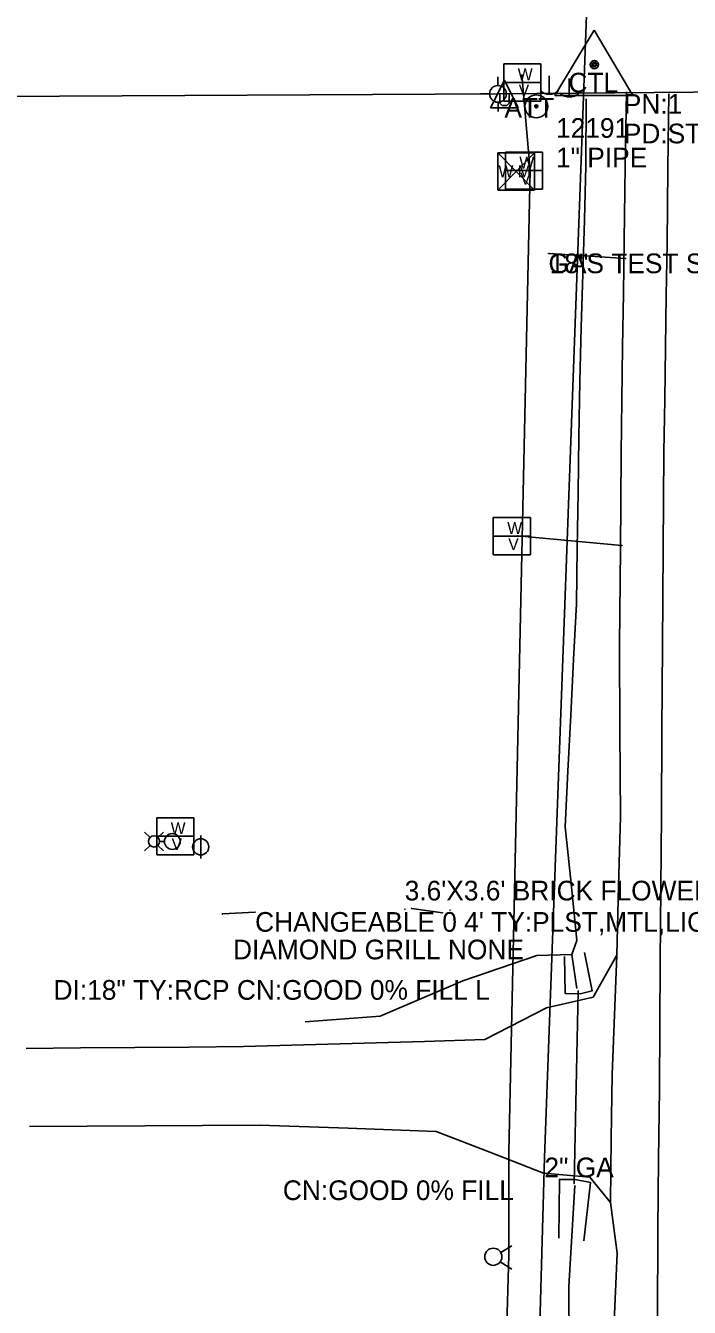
# Model space of a CAD drawing. Extents: x 1707085 to 1720058, y 548761 to 560063.
# Drawn here: x 1712324.4 to 1712493.1, y 550824.4 to 551149.9 of the extents above; entities that cross this region are included whole.
import ezdxf

# ---------------------------------------------------------------- set-up
doc = ezdxf.new("R2010")
doc.units = 0
for name, color, linetype in [('3', 7, 'Continuous'), ('R_Contour Annot', 7, 'Continuous'), ('R_Horz Alg Annot', 7, 'Continuous'), ('R_Water Annot', 7, 'Continuous'), ('S_DRG_PT_SYM', 7, 'Continuous'), ('S_DRIVEWAY', 7, 'Continuous'), ('S_EDGE_CONCRETE', 7, 'Continuous'), ('S_EDGE_PAVEMENT', 7, 'Continuous'), ('S_GAS_UTILITIES', 7, 'Continuous'), ('S_GAS_UTILITIES_ANNOT', 7, 'Continuous'), ('S_IRON_PIN', 7, 'Continuous'), ('S_IRON_PIN_ANNOT', 7, 'Continuous'), ('S_MISC_STRUCTURES_ANNOT', 7, 'Continuous'), ('S_MSC_PT_SYM', 7, 'Continuous'), ('S_PAVEMENT_CROWN', 7, 'Continuous'), ('S_PRIMARY_CTL_ANNOT', 7, 'Continuous'), ('S_SIDE_DRAIN_ANNOT', 7, 'Continuous'), ('S_SIGN_ANNOT', 7, 'Continuous'), ('S_UNDERGROUND_CABLE', 7, 'Continuous'), ('S_UTILITY_POLE', 7, 'Continuous'), ('S_UTILITY_POLE_ANNOT', 7, 'Continuous'), ('S_UTL_PT_SYM', 7, 'Continuous')]:
    doc.layers.add(name, color=color, linetype=linetype)

msp = doc.modelspace()

# ---------------------------------------------------------------- linework, layer by layer
for points in [[(1712464.5, 550905.39), (1712463.25, 550914.02), (1712464.48, 550917.63), (1712463.01, 550932.04), (1712461.53, 550946.44), (1712462.24, 550960.61), (1712462.94, 550974.77), (1712463.65, 550988.93), (1712464.36, 551003.09), (1712464.57, 551017.21), (1712464.79, 551031.33), (1712465.01, 551045.44), (1712465.23, 551059.56), (1712465.62, 551073.23), (1712466.02, 551086.9), (1712466.41, 551100.57), (1712466.81, 551114.24), (1712466.83, 551131.33)], [(1712463.25, 550914.02), (1712454.36, 550913.82), (1712435.52, 550907.35), (1712414.54, 550898.36), (1712395.46, 550896.92)], [(1712463.94, 550855.4), (1712463.2, 550842.56), (1712462.46, 550829.72), (1712462.55, 550815.13), (1712462.64, 550800.54), (1712462.46, 550798.31), (1712462.44, 550791.97), (1712462.37, 550776.28), (1712462.3, 550760.58), (1712462.68, 550740.27), (1712463.06, 550719.96), (1712463.44, 550699.64), (1712463.81, 550679.33), (1712464.04, 550656.46), (1712464.27, 550633.6), (1712455.29, 550618.31)]]:
    msp.add_lwpolyline(points)
at = {"layer": '3'}
msp.add_line((1712464.83, 550904.77), (1712463.8, 550855.94), dxfattribs=at)
at = {"layer": 'R_Contour Annot'}
for p, q in [((1712468.92, 551148.69), (1712458.89, 551132.17)), ((1712468.92, 551148.69), (1712478.75, 551132.17)), ((1712458.89, 551132.17), (1712478.75, 551132.17))]:
    msp.add_line(p, q, dxfattribs=at)
for radius in [1.04, 0.609, 0.344]:
    msp.add_circle((1712468.92, 551139.99), radius, dxfattribs=at)
at = {"layer": 'R_Horz Alg Annot'}
for p, q in [((1712430.31, 550924.65), (1712422.52, 550925.73)), ((1712382.73, 550924.81), (1712374.42, 550924.33))]:
    msp.add_line(p, q, dxfattribs=at)
at = {"layer": 'R_Water Annot'}
for p, q in [((1712445.92, 551140.15), (1712455.34, 551140.15)), ((1712445.92, 551130.74), (1712445.92, 551140.15)), ((1712455.34, 551140.15), (1712455.34, 551130.74)), ((1712452.6, 551113.03), (1712450.52, 551137.37)), ((1712445.92, 551135.47), (1712455.34, 551135.47)), ((1712455.34, 551130.74), (1712445.92, 551130.74)), ((1712444.37, 551117.62), (1712453.71, 551117.62)), ((1712444.37, 551117.62), (1712444.37, 551108.13)), ((1712444.37, 551117.62), (1712453.71, 551108.13)), ((1712453.71, 551117.62), (1712444.37, 551108.13)), ((1712446.32, 551117.74), (1712455.74, 551117.74)), ((1712446.32, 551108.33), (1712446.32, 551117.74)), ((1712453.71, 551117.62), (1712453.71, 551108.13)), ((1712455.74, 551117.74), (1712455.74, 551108.33)), ((1712446.32, 551113.06), (1712455.74, 551113.06)), ((1712447.18, 550863.91), (1712452.6, 551113.03)), ((1712444.37, 551108.13), (1712453.71, 551108.13)), ((1712455.74, 551108.33), (1712446.32, 551108.33)), ((1712443.26, 551024.96), (1712452.68, 551024.96)), ((1712443.26, 551015.55), (1712443.26, 551024.96)), ((1712452.68, 551024.96), (1712452.68, 551015.55)), ((1712443.26, 551020.28), (1712452.68, 551020.28)), ((1712449.37, 551020.3), (1712475.96, 551017.85)), ((1712452.68, 551015.55), (1712443.26, 551015.55)), ((1712357.72, 550948.78), (1712367.13, 550948.78)), ((1712357.72, 550939.37), (1712357.72, 550948.78)), ((1712367.13, 550948.78), (1712367.13, 550939.37)), ((1712357.72, 550944.09), (1712367.13, 550944.09)), ((1712367.13, 550939.37), (1712357.72, 550939.37)), ((1712447.19, 550837.71), (1712447.18, 550863.91)), ((1712445.16, 550838.36), (1712447.98, 550840.09)), ((1712446.27, 550804), (1712447.19, 550837.71)), ((1712445.03, 550836.05), (1712447.94, 550834.12))]:
    msp.add_line(p, q, dxfattribs=at)
msp.add_circle((1712443.25, 550837.3), 2.18, dxfattribs=at)
at = {"layer": 'S_DRG_PT_SYM'}
for points in [[(1712464.83, 550904.77), (1712464.83, 550904.82), (1712464.83, 550904.77), (1712464.78, 550904.77), (1712464.83, 550904.77), (1712464.83, 550904.72), (1712464.83, 550904.77), (1712464.88, 550904.77)], [(1712463.8, 550855.94), (1712463.8, 550855.99), (1712463.8, 550855.94), (1712463.75, 550855.94), (1712463.8, 550855.94), (1712463.8, 550855.89), (1712463.8, 550855.94), (1712463.85, 550855.94)]]:
    msp.add_lwpolyline(points, dxfattribs=at)
at = {"layer": 'S_DRIVEWAY'}
for points in [[(1712324.57, 550890.19), (1712338.36, 550890.31), (1712352.16, 550890.43), (1712365.95, 550890.55), (1712379.74, 550890.67), (1712395.09, 550891.11), (1712410.44, 550891.55), (1712425.79, 550891.99), (1712441.14, 550892.43), (1712456.77, 550900.53), (1712468.64, 550903.23), (1712474.64, 550913.89)], [(1712473.03, 550851.08), (1712467.79, 550857.49), (1712455.99, 550858.53), (1712442.36, 550863.82), (1712428.73, 550869.12), (1712406.35, 550869.92), (1712383.97, 550870.71), (1712369.34, 550870.62), (1712354.71, 550870.53), (1712340.08, 550870.44), (1712325.44, 550870.35)]]:
    msp.add_lwpolyline(points, dxfattribs=at)
at = {"layer": 'S_EDGE_CONCRETE'}
for points in [[(1712461.36, 550913.56), (1712461.5, 550904.18), (1712465.31, 550904.06), (1712468.42, 550904.84), (1712466.46, 550914.55)], [(1712459.94, 550842.02), (1712460.08, 550856.92), (1712464.09, 550856.95), (1712467.97, 550856.15), (1712466.25, 550841.33)]]:
    msp.add_lwpolyline(points, dxfattribs=at)
at = {"layer": 'S_EDGE_PAVEMENT'}
msp.add_lwpolyline([(1712477.08, 551133.03), (1712476.81, 551114.23), (1712476.55, 551095.42), (1712476.34, 551081.87), (1712476.13, 551068.31), (1712475.92, 551054.75), (1712475.71, 551041.2), (1712475.54, 551016.98), (1712475.36, 550992.76), (1712475.45, 550970.88), (1712475.54, 550949), (1712475.09, 550931.44), (1712474.64, 550913.89), (1712474.06, 550898.74), (1712473.47, 550883.58), (1712473.25, 550867.33), (1712473.03, 550851.08), (1712474.71, 550838.17), (1712473.92, 550818.83)], dxfattribs=at)
at = {"layer": 'S_GAS_UTILITIES'}
for p, q in [((1712471.24, 551268.07), (1712456.25, 550862.48)), ((1712457.58, 551092.02), (1712476.87, 551090.75)), ((1712456.25, 550862.48), (1712454.33, 550794.95))]:
    msp.add_line(p, q, dxfattribs=at)
at = {"layer": 'S_IRON_PIN'}
for radius in [2.91, 0.411, 0.262, 0.212, 0.145, 0.0822, 0.0581]:
    msp.add_circle((1712454.19, 551129.39), radius, dxfattribs=at)
at = {"layer": 'S_MSC_PT_SYM'}
for points in [[(1712457.27, 551092.02), (1712457.27, 551092.07), (1712457.27, 551092.02), (1712457.22, 551092.02), (1712457.27, 551092.02), (1712457.27, 551091.97), (1712457.27, 551092.02), (1712457.32, 551092.02)], [(1712420.81, 550925.53), (1712420.81, 550925.58), (1712420.81, 550925.53), (1712420.76, 550925.53), (1712420.81, 550925.53), (1712420.81, 550925.48), (1712420.81, 550925.53), (1712420.86, 550925.53)], [(1712422.52, 550925.73), (1712422.52, 550925.78), (1712422.52, 550925.73), (1712422.47, 550925.73), (1712422.52, 550925.73), (1712422.52, 550925.68), (1712422.52, 550925.73), (1712422.57, 550925.73)], [(1712432.28, 550925.33), (1712432.28, 550925.38), (1712432.28, 550925.33), (1712432.23, 550925.33), (1712432.28, 550925.33), (1712432.28, 550925.28), (1712432.28, 550925.33), (1712432.33, 550925.33)], [(1712374.42, 550924.33), (1712374.42, 550924.38), (1712374.42, 550924.33), (1712374.37, 550924.33), (1712374.42, 550924.33), (1712374.42, 550924.28), (1712374.42, 550924.33), (1712374.47, 550924.33)], [(1712382.73, 550924.81), (1712382.73, 550924.86), (1712382.73, 550924.81), (1712382.68, 550924.81), (1712382.73, 550924.81), (1712382.73, 550924.76), (1712382.73, 550924.81), (1712382.78, 550924.81)], [(1712430.31, 550924.65), (1712430.31, 550924.7), (1712430.31, 550924.65), (1712430.26, 550924.65), (1712430.31, 550924.65), (1712430.31, 550924.6), (1712430.31, 550924.65), (1712430.36, 550924.65)]]:
    msp.add_lwpolyline(points, dxfattribs=at)
at = {"layer": 'S_PAVEMENT_CROWN'}
msp.add_lwpolyline([(1712484.99, 550821.29), (1712485.11, 550844.3), (1712485.28, 550862.1), (1712485.46, 550879.89), (1712485.58, 550896.07), (1712485.7, 550912.25), (1712485.83, 550930.86), (1712485.96, 550949.48), (1712486.1, 550970.94), (1712486.23, 550992.4), (1712486.43, 551017.02), (1712486.63, 551041.65), (1712486.83, 551054.88), (1712487.02, 551068.12), (1712487.22, 551081.36), (1712487.42, 551094.6), (1712487.65, 551113.6), (1712487.87, 551132.6)], dxfattribs=at)
at = {"layer": 'S_UNDERGROUND_CABLE'}
for p, q in [((1712446.09, 551136.07), (1712442.56, 551128.98)), ((1712446.09, 551136.07), (1712449.58, 551128.98)), ((1712444.89, 551130.22), (1712444.89, 551132.66)), ((1712447.25, 551132.66), (1712447.25, 551130.22)), ((1712442.56, 551128.98), (1712449.58, 551128.98)), ((1712445.51, 551129.56), (1712444.89, 551130.22)), ((1712446.71, 551129.56), (1712445.51, 551129.56)), ((1712447.25, 551130.22), (1712446.71, 551129.56))]:
    msp.add_line(p, q, dxfattribs=at)
at = {"layer": 'S_UTILITY_POLE'}
for p, q in [((1712444.45, 551134.65), (1712444.45, 551136.9)), ((1712457.42, 551137.14), (1712457.42, 551132.41)), ((1712462.56, 551136.48), (1712462.56, 551131.76)), ((1712444.45, 551132.54), (1712153.66, 551130.97)), ((1712442.35, 551132.52), (1712440.03, 551132.52)), ((1712444.52, 551128.1), (1712444.52, 551130.43)), ((1712356.03, 550943.75), (1712354.66, 550945.11)), ((1712358.05, 550943.75), (1712359.41, 550945.11)), ((1712354.66, 550940.36), (1712356.03, 550941.73)), ((1712359.41, 550940.36), (1712358.05, 550941.73)), ((1712358.46, 550942.74), (1712359.69, 550942.74)), ((1712368.91, 550938.44), (1712368.91, 550944.23))]:
    msp.add_line(p, q, dxfattribs=at)
msp.add_lwpolyline([(1712497.7, 549518.48), (1712500.91, 549949.57), (1712500.58, 550149.34), (1712502.49, 550416.34), (1712509.79, 550634.49), (1712512.76, 550903.53), (1712513.37, 551033.49), (1712513.87, 551133.13), (1712444.45, 551132.54)], dxfattribs=at)
for centre, radius in [((1712444.45, 551132.54), 2.13), ((1712357.04, 550942.74), 1.43), ((1712361.69, 550942.74), 2), ((1712368.91, 550941.37), 2.05)]:
    msp.add_circle(centre, radius, dxfattribs=at)
for centre in [(1712457.48, 551135.84), (1712462.62, 551135.18)]:
    msp.add_arc(centre, 3.41, 226.3972, 313.6028, dxfattribs=at)
at = {"layer": 'S_UTL_PT_SYM'}
for points in [[(1712450.52, 551137.37), (1712450.52, 551137.42), (1712450.52, 551137.37), (1712450.47, 551137.37), (1712450.52, 551137.37), (1712450.52, 551137.32), (1712450.52, 551137.37), (1712450.57, 551137.37)], [(1712452.6, 551113.03), (1712452.6, 551113.08), (1712452.6, 551113.03), (1712452.55, 551113.03), (1712452.6, 551113.03), (1712452.6, 551112.98), (1712452.6, 551113.03), (1712452.65, 551113.03)], [(1712457.58, 551092.02), (1712457.58, 551092.07), (1712457.58, 551092.02), (1712457.53, 551092.02), (1712457.58, 551092.02), (1712457.58, 551091.97), (1712457.58, 551092.02), (1712457.63, 551092.02)], [(1712476.87, 551090.75), (1712476.87, 551090.8), (1712476.87, 551090.75), (1712476.82, 551090.75), (1712476.87, 551090.75), (1712476.87, 551090.7), (1712476.87, 551090.75), (1712476.92, 551090.75)], [(1712449.37, 551020.3), (1712449.37, 551020.35), (1712449.37, 551020.3), (1712449.32, 551020.3), (1712449.37, 551020.3), (1712449.37, 551020.25), (1712449.37, 551020.3), (1712449.42, 551020.3)], [(1712475.96, 551017.85), (1712475.96, 551017.9), (1712475.96, 551017.85), (1712475.91, 551017.85), (1712475.96, 551017.85), (1712475.96, 551017.8), (1712475.96, 551017.85), (1712476.01, 551017.85)], [(1712447.18, 550863.91), (1712447.18, 550863.96), (1712447.18, 550863.91), (1712447.13, 550863.91), (1712447.18, 550863.91), (1712447.18, 550863.86), (1712447.18, 550863.91), (1712447.23, 550863.91)], [(1712456.25, 550862.48), (1712456.25, 550862.53), (1712456.25, 550862.48), (1712456.2, 550862.48), (1712456.25, 550862.48), (1712456.25, 550862.43), (1712456.25, 550862.48), (1712456.3, 550862.48)], [(1712447.19, 550837.71), (1712447.19, 550837.76), (1712447.19, 550837.71), (1712447.14, 550837.71), (1712447.19, 550837.71), (1712447.19, 550837.66), (1712447.19, 550837.71), (1712447.24, 550837.71)]]:
    msp.add_lwpolyline(points, dxfattribs=at)

# ---------------------------------------------------------------- texts
at = {"layer": 'R_Contour Annot'}
msp.add_text('CTL', height=5, rotation=360, dxfattribs=at).set_placement((1712462.34, 551132.91))
at = {"layer": 'R_Water Annot'}
for s, p in [('W', (1712449.47, 551136)), ('V', (1712449.71, 551131.93)), ('W M', (1712444.57, 551111.39)), ('W', (1712449.87, 551113.59)), ('V', (1712450.11, 551109.52)), ('W', (1712446.81, 551020.81)), ('V', (1712447.05, 551016.74)), ('W', (1712361.27, 550944.62)), ('V', (1712361.5, 550940.56))]:
    msp.add_text(s, height=3, rotation=360, dxfattribs=at).set_placement(p)
at = {"layer": 'S_GAS_UTILITIES_ANNOT'}
for s, p in [('18"', (1712457.58, 551087.02)), ('2" GA', (1712456.25, 550857.48))]:
    msp.add_text(s, height=5, dxfattribs=at).set_placement(p)
at = {"layer": 'S_IRON_PIN_ANNOT'}
for s, p in [('12191', (1712459.19, 551121.39)), ('1" PIPE', (1712459.19, 551113.89))]:
    msp.add_text(s, height=5, dxfattribs=at).set_placement(p)
at = {"layer": 'S_MISC_STRUCTURES_ANNOT'}
for s, p in [('GAS TEST STATION', (1712457.27, 551087.02)), ("3.6'X3.6' BRICK FLOWERBED", (1712420.74, 550927.76))]:
    msp.add_text(s, height=5, dxfattribs=at).set_placement(p)
at = {"layer": 'S_PRIMARY_CTL_ANNOT'}
for s, p in [('PN:1', (1712476.42, 551127.49)), ('PD:STD AHTD MON. STAMPED PN:1 JONESBORO', (1712476.42, 551119.99))]:
    msp.add_text(s, height=5, dxfattribs=at).set_placement(p)
at = {"layer": 'S_SIDE_DRAIN_ANNOT'}
for s, p in [('DI:18" TY:RCP CN:GOOD 0% FILL L', (1712331.51, 550902.55)), ('CN:GOOD 0% FILL', (1712389.78, 550851.69))]:
    msp.add_text(s, height=5, dxfattribs=at).set_placement(p)
at = {"layer": 'S_SIGN_ANNOT'}
for s, p in [("CHANGEABLE 0 4' TY:PLST,MTL,LIGHTED", (1712382.73, 550919.81)), ('DIAMOND GRILL NONE', (1712377.12, 550912.81))]:
    msp.add_text(s, height=5, dxfattribs=at).set_placement(p)
at = {"layer": 'S_UTILITY_POLE_ANNOT'}
msp.add_text('ATT', height=5, dxfattribs=at).set_placement((1712446.09, 551126.54))

doc.saveas('drawing.dxf')
